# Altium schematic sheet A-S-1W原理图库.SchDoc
size 127 x 99 mm
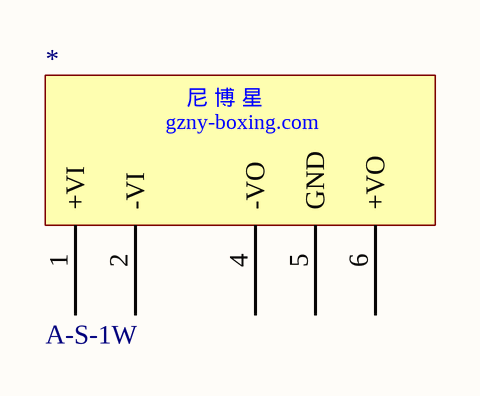
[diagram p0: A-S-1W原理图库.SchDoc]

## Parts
*  A-S-1W

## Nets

Not connected (* = marked no-connect by the designer): * 1(+VI) 2(-VI) 4(-VO) 5(GND) 6(+VO)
